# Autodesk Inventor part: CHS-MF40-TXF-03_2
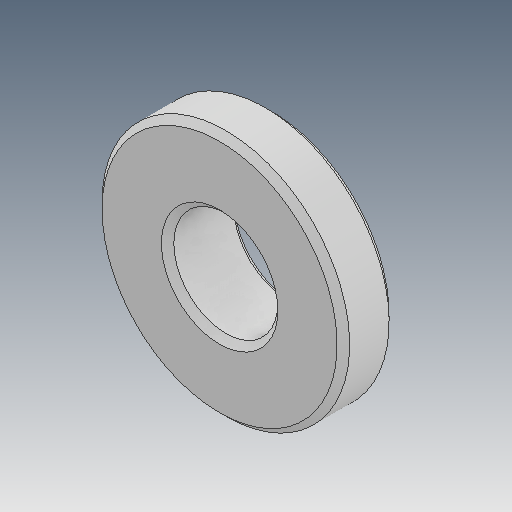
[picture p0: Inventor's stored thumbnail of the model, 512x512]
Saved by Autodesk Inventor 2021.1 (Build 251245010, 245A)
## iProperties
Created: 2019-04
Part Number: CHS-MF40-TXF-03_2
Material: Ogólny
Document SubType Name: Modeling
Designer: user
Density: 1 g/cm^3
Appearance: Domyślna
Author: user
Revision Number: ÈÎºÎ
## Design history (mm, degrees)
feature "ÊäÈë1"
node "Bryła1"
